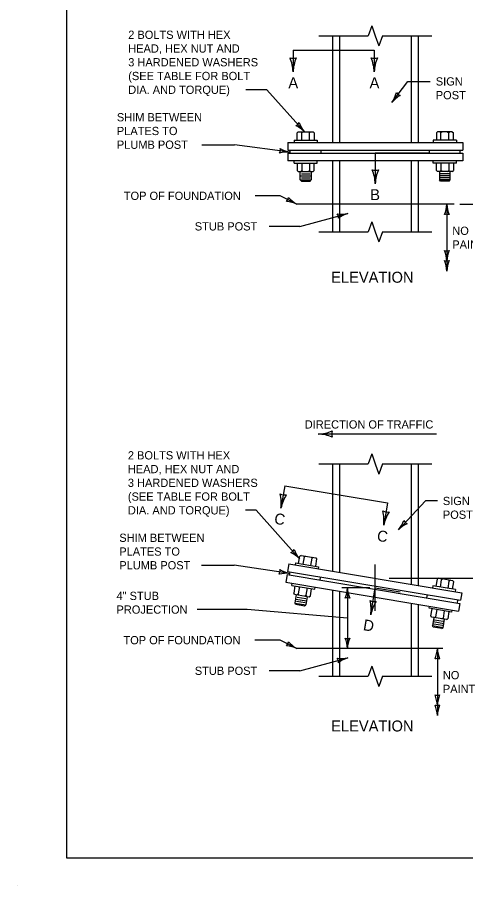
# Model space of a CAD drawing. Extents: x 49991.4 to 50021, y 49987.6 to 50011.4.
# Drawn here: x 49999.02 to 50002.29, y 49987.6 to 49993.92 of the extents above; entities that cross this region are included whole.
import ezdxf

# ---------------------------------------------------------------- set-up
doc = ezdxf.new("R2010")
doc.units = 0
for name, color, linetype in [('Level 1', 7, 'Continuous'), ('Level 2', 7, 'Continuous'), ('Level 3', 7, 'Continuous'), ('Level 5', 7, 'Continuous'), ('Level 6', 7, 'Continuous')]:
    doc.layers.add(name, color=color, linetype=linetype)

msp = doc.modelspace()

# ---------------------------------------------------------------- linework, layer by layer
at = {"layer": 'Level 1'}
for p, q in [((50001.3176, 49993.7824), (50001.3176, 49993.0073)), ((50001.3693, 49993.7824), (50001.3693, 49993.0073)), ((50001.8899, 49993.7824), (50001.8899, 49993.0073)), ((50001.9416, 49993.7824), (50001.9416, 49993.0073)), ((50001.069, 49993.0832), (50001.0615, 49993.0757)), ((50001.0615, 49993.0223), (50001.0615, 49993.0757)), ((50001.069, 49993.0832), (50001.1777, 49993.0832)), ((50001.0877, 49993.0832), (50001.0952, 49993.0757)), ((50001.1028, 49993.0832), (50001.0952, 49993.0757)), ((50001.0952, 49993.0223), (50001.0952, 49993.0757)), ((50001.144, 49993.0832), (50001.1515, 49993.0757)), ((50001.159, 49993.0832), (50001.1515, 49993.0757)), ((50001.1515, 49993.0223), (50001.1515, 49993.0757)), ((50001.1777, 49993.0832), (50001.1852, 49993.0757)), ((50001.1852, 49993.0757), (50001.1852, 49993.0223)), ((50002.0815, 49993.0832), (50002.074, 49993.0757)), ((50002.074, 49993.0757), (50002.074, 49993.0223)), ((50002.1902, 49993.0832), (50002.0815, 49993.0832)), ((50002.1002, 49993.0832), (50002.1077, 49993.0757)), ((50002.1152, 49993.0832), (50002.1077, 49993.0757)), ((50002.1077, 49993.0223), (50002.1077, 49993.0757)), ((50002.1564, 49993.0832), (50002.164, 49993.0757)), ((50002.1715, 49993.0832), (50002.164, 49993.0757)), ((50002.164, 49993.0223), (50002.164, 49993.0757)), ((50002.1902, 49993.0832), (50002.1977, 49993.0757)), ((50002.1977, 49993.0223), (50002.1977, 49993.0757)), ((50000.9922, 49993.0073), (50002.267, 49993.0073)), ((50000.9922, 49993.0073), (50000.9922, 49992.9512)), ((50001.039, 49993.0223), (50001.2077, 49993.0223)), ((50001.039, 49993.0223), (50001.039, 49993.0073)), ((50001.2077, 49993.0223), (50001.2077, 49993.0073)), ((50002.2202, 49993.0223), (50002.0515, 49993.0223)), ((50002.0515, 49993.0223), (50002.0515, 49993.0073)), ((50002.2202, 49993.0223), (50002.2202, 49993.0073)), ((50002.267, 49993.0073), (50002.267, 49992.9512)), ((50000.9922, 49992.9512), (50002.267, 49992.9512)), ((50000.9922, 49992.928), (50002.267, 49992.928)), ((50000.9922, 49992.928), (50000.9922, 49992.8717)), ((50001.0109, 49992.928), (50001.0109, 49992.9512)), ((50001.2359, 49992.928), (50001.2359, 49992.9512)), ((50002.0233, 49992.928), (50002.0233, 49992.9512)), ((50002.2483, 49992.928), (50002.2483, 49992.9512)), ((50002.267, 49992.928), (50002.267, 49992.8717)), ((50002.267, 49992.8717), (50000.9922, 49992.8717)), ((50001.039, 49992.8568), (50001.039, 49992.8717)), ((50001.039, 49992.8568), (50001.2077, 49992.8568)), ((50001.0615, 49992.8568), (50001.0615, 49992.8033)), ((50001.0952, 49992.8568), (50001.0952, 49992.8033)), ((50001.1515, 49992.8568), (50001.1515, 49992.8033)), ((50001.1852, 49992.8033), (50001.1852, 49992.8568)), ((50001.2077, 49992.8568), (50001.2077, 49992.8717)), ((50001.3176, 49992.8717), (50001.3176, 49992.3555)), ((50001.3693, 49992.8717), (50001.3693, 49992.3555)), ((50001.8899, 49992.8717), (50001.8899, 49992.3555)), ((50001.9416, 49992.8717), (50001.9416, 49992.3555)), ((50002.0515, 49992.8568), (50002.0515, 49992.8717)), ((50002.2202, 49992.8568), (50002.0515, 49992.8568)), ((50002.074, 49992.8033), (50002.074, 49992.8568)), ((50002.1077, 49992.8568), (50002.1077, 49992.8033)), ((50002.164, 49992.8568), (50002.164, 49992.8033)), ((50002.1977, 49992.8568), (50002.1977, 49992.8033)), ((50002.2202, 49992.8568), (50002.2202, 49992.8717)), ((50001.069, 49992.7959), (50001.0615, 49992.8033)), ((50001.069, 49992.7959), (50001.1777, 49992.7959)), ((50001.084, 49992.7335), (50001.084, 49992.7959)), ((50001.0877, 49992.7959), (50001.0952, 49992.8033)), ((50001.1028, 49992.7959), (50001.0952, 49992.8033)), ((50001.144, 49992.7959), (50001.1515, 49992.8033)), ((50001.159, 49992.7959), (50001.1515, 49992.8033)), ((50001.1628, 49992.7959), (50001.1628, 49992.7335)), ((50001.1777, 49992.7959), (50001.1852, 49992.8033)), ((50002.0815, 49992.7959), (50002.074, 49992.8033)), ((50002.1902, 49992.7959), (50002.0815, 49992.7959)), ((50002.0964, 49992.7959), (50002.0964, 49992.7335)), ((50002.1002, 49992.7959), (50002.1077, 49992.8033)), ((50002.1152, 49992.7959), (50002.1077, 49992.8033)), ((50002.1564, 49992.7959), (50002.164, 49992.8033)), ((50002.1715, 49992.7959), (50002.164, 49992.8033)), ((50002.1752, 49992.7335), (50002.1752, 49992.7959)), ((50002.1902, 49992.7959), (50002.1977, 49992.8033)), ((50001.084, 49992.7635), (50001.1628, 49992.7635)), ((50001.0915, 49992.7259), (50001.084, 49992.7335)), ((50001.084, 49992.7335), (50001.1628, 49992.7335)), ((50001.0915, 49992.7784), (50001.1552, 49992.7784)), ((50001.0915, 49992.7484), (50001.1552, 49992.7484)), ((50001.0915, 49992.7259), (50001.1552, 49992.7259)), ((50001.1552, 49992.7259), (50001.1628, 49992.7335)), ((50002.1752, 49992.7635), (50002.0964, 49992.7635)), ((50002.104, 49992.7259), (50002.0964, 49992.7335)), ((50002.1752, 49992.7335), (50002.0964, 49992.7335)), ((50002.1677, 49992.7784), (50002.104, 49992.7784)), ((50002.1677, 49992.7484), (50002.104, 49992.7484)), ((50002.1677, 49992.7259), (50002.104, 49992.7259)), ((50002.1677, 49992.7259), (50002.1752, 49992.7335)), ((50002.2046, 49992.5575), (50001.0586, 49992.5575)), ((50001.3176, 49990.6669), (50001.3176, 49989.8871)), ((50001.3693, 49990.6669), (50001.3693, 49989.8784)), ((50001.8899, 49990.6669), (50001.8899, 49989.7918)), ((50001.9416, 49990.6669), (50001.9416, 49989.7832)), ((50001.0494, 49989.9471), (50001.047, 49989.9322)), ((50001.0494, 49989.9471), (50001.216, 49989.9192)), ((50001.0717, 49989.9432), (50001.0804, 49989.996)), ((50001.089, 49990.0022), (50001.0804, 49989.996)), ((50001.089, 49990.0022), (50001.1963, 49989.9843)), ((50001.105, 49989.9377), (50001.1137, 49989.9904)), ((50001.1076, 49989.999), (50001.1137, 49989.9904)), ((50001.1224, 49989.9965), (50001.1137, 49989.9904)), ((50001.1605, 49989.9286), (50001.1692, 49989.9812)), ((50001.163, 49989.9898), (50001.1692, 49989.9812)), ((50001.1778, 49989.9874), (50001.1692, 49989.9812)), ((50001.2025, 49989.9756), (50001.1938, 49989.923)), ((50001.1963, 49989.9843), (50001.2025, 49989.9756)), ((50001.0008, 49989.9399), (50000.9916, 49989.8844)), ((50000.9916, 49989.8844), (50002.2492, 49989.6749)), ((50001.0008, 49989.9399), (50002.2584, 49989.7304)), ((50001.0062, 49989.8585), (50001.01, 49989.8813)), ((50001.216, 49989.9192), (50001.2134, 49989.9045)), ((50000.9877, 49989.8616), (50000.9785, 49989.8062)), ((50000.9877, 49989.8616), (50002.2453, 49989.6521)), ((50001.2282, 49989.8216), (50001.232, 49989.8444)), ((50002.0792, 49989.8296), (50002.0704, 49989.7769)), ((50002.0879, 49989.8357), (50002.0792, 49989.8296)), ((50002.195, 49989.8178), (50002.0879, 49989.8357)), ((50002.1037, 49989.7714), (50002.1125, 49989.824)), ((50002.1064, 49989.8326), (50002.1125, 49989.824)), ((50002.1211, 49989.8302), (50002.1125, 49989.824)), ((50002.1618, 49989.8235), (50002.1679, 49989.8148)), ((50002.1766, 49989.821), (50002.1679, 49989.8148)), ((50002.195, 49989.8178), (50002.2012, 49989.8092)), ((50000.9785, 49989.8062), (50002.2362, 49989.5967)), ((50001.0223, 49989.7836), (50001.0247, 49989.7985)), ((50001.0223, 49989.7836), (50001.1887, 49989.7559)), ((50001.0445, 49989.78), (50001.0357, 49989.7274)), ((50001.0777, 49989.7745), (50001.069, 49989.7217)), ((50001.1332, 49989.7652), (50001.1245, 49989.7126)), ((50001.1578, 49989.707), (50001.1665, 49989.7596)), ((50001.1887, 49989.7559), (50001.1912, 49989.7707)), ((50002.0483, 49989.7806), (50002.0458, 49989.7659)), ((50002.2146, 49989.7529), (50002.0483, 49989.7806)), ((50002.1592, 49989.762), (50002.1679, 49989.8148)), ((50002.1925, 49989.7565), (50002.2012, 49989.8092)), ((50002.2146, 49989.7529), (50002.2122, 49989.738)), ((50001.0418, 49989.7187), (50001.0357, 49989.7274)), ((50001.0418, 49989.7187), (50001.1491, 49989.7008)), ((50001.0464, 49989.6546), (50001.0566, 49989.7162)), ((50001.0603, 49989.7156), (50001.069, 49989.7217)), ((50001.0612, 49989.6977), (50001.124, 49989.6873)), ((50001.0751, 49989.7131), (50001.069, 49989.7217)), ((50001.1159, 49989.7064), (50001.1245, 49989.7126)), ((50001.1344, 49989.7032), (50001.124, 49989.6417)), ((50001.1306, 49989.704), (50001.1245, 49989.7126)), ((50001.1491, 49989.7008), (50001.1578, 49989.707)), ((50001.3176, 49989.7497), (50001.3176, 49989.122)), ((50001.3693, 49989.741), (50001.3693, 49989.122)), ((50002.005, 49989.6922), (50002.0087, 49989.715)), ((50002.2584, 49989.7304), (50002.2492, 49989.6749)), ((50001.0525, 49989.646), (50001.0464, 49989.6546)), ((50001.0464, 49989.6546), (50001.124, 49989.6417)), ((50001.0513, 49989.6843), (50001.129, 49989.6713)), ((50001.0525, 49989.646), (50001.1154, 49989.6356)), ((50001.0562, 49989.6682), (50001.1191, 49989.6578)), ((50001.1154, 49989.6356), (50001.124, 49989.6417)), ((50001.8899, 49989.6543), (50001.8899, 49989.122)), ((50001.9416, 49989.6456), (50001.9416, 49989.122)), ((50002.0209, 49989.6173), (50002.0234, 49989.6321)), ((50002.2268, 49989.6552), (50002.2307, 49989.678)), ((50002.2453, 49989.6521), (50002.2362, 49989.5967)), ((50002.1875, 49989.5895), (50002.0209, 49989.6173)), ((50002.0344, 49989.5609), (50002.0432, 49989.6136)), ((50002.0765, 49989.608), (50002.0677, 49989.5554)), ((50002.132, 49989.5988), (50002.1232, 49989.5462)), ((50002.1653, 49989.5932), (50002.1565, 49989.5405)), ((50002.1875, 49989.5895), (50002.1899, 49989.6044)), ((50002.0406, 49989.5523), (50002.0344, 49989.5609)), ((50002.1479, 49989.5344), (50002.0406, 49989.5523)), ((50002.0554, 49989.5499), (50002.0452, 49989.4882)), ((50002.1277, 49989.5049), (50002.05, 49989.5178)), ((50002.1179, 49989.4913), (50002.055, 49989.5018)), ((50002.0591, 49989.5492), (50002.0677, 49989.5554)), ((50002.1228, 49989.5208), (50002.0599, 49989.5314)), ((50002.0738, 49989.5468), (50002.0677, 49989.5554)), ((50002.1145, 49989.54), (50002.1232, 49989.5462)), ((50002.1228, 49989.4752), (50002.133, 49989.5369)), ((50002.1294, 49989.5375), (50002.1232, 49989.5462)), ((50002.1479, 49989.5344), (50002.1565, 49989.5405)), ((50002.0513, 49989.4796), (50002.0452, 49989.4882)), ((50002.1228, 49989.4752), (50002.0452, 49989.4882)), ((50002.1142, 49989.4691), (50002.0513, 49989.4796)), ((50002.1142, 49989.4691), (50002.1228, 49989.4752)), ((50002.1214, 49989.324), (50001.0586, 49989.324)), ((49999.0245, 49987.5988), (49999.0245, 49987.5988))]:
    msp.add_line(p, q, dxfattribs=at)
msp.add_lwpolyline([(49999.3835, 49998.9992), (50016.7501, 49998.9992), (50016.7501, 49987.7988), (49999.3835, 49987.7988)], close=True, dxfattribs=at)
at = {"layer": 'Level 3'}
for p, q in [((50001.7508, 49993.298), (50001.8658, 49993.4507)), ((50001.8658, 49993.4507), (50002.0299, 49993.4507)), ((50000.8398, 49993.3901), (50000.6876, 49993.3901)), ((50001.1148, 49993.0832), (50000.8398, 49993.3901)), ((50000.3679, 49992.9901), (50000.6057, 49992.9901)), ((50001.0109, 49992.9354), (50000.6057, 49992.9901)), ((50000.9384, 49992.6184), (50000.756, 49992.6184)), ((50001.0586, 49992.5575), (50000.9384, 49992.6184)), ((50002.1501, 49992.5575), (50002.1501, 49992.0704)), ((50002.2446, 49992.5575), (50002.5649, 49992.5575)), ((50001.0796, 49992.3959), (50001.4302, 49992.4906)), ((50001.0796, 49992.3959), (50000.8577, 49992.3959)), ((50002.0762, 49990.8848), (50001.2147, 49990.8848)), ((50001.9939, 49990.3979), (50001.7983, 49990.1885)), ((50002.0814, 49990.3979), (50001.9939, 49990.3979)), ((50000.7619, 49990.3299), (50000.685, 49990.3299)), ((50001.0772, 49989.9768), (50000.7619, 49990.3299)), ((50000.3653, 49989.9299), (50000.6029, 49989.9299)), ((50001.0082, 49989.8704), (50000.6029, 49989.9299)), ((50001.7296, 49989.8352), (50002.4683, 49989.8352)), ((50001.5896, 49989.7664), (50001.3867, 49989.7664)), ((50001.4267, 49989.7664), (50001.4267, 49989.324)), ((50000.6981, 49989.6074), (50000.3334, 49989.6074)), ((50001.4267, 49989.5452), (50000.6981, 49989.6074)), ((50000.9384, 49989.3849), (50000.7534, 49989.3849)), ((50001.0586, 49989.324), (50000.9384, 49989.3849)), ((50002.0814, 49989.324), (50002.0814, 49988.8369)), ((50001.0796, 49989.1624), (50001.4302, 49989.2571)), ((50001.0796, 49989.1624), (50000.8577, 49989.1624))]:
    msp.add_line(p, q, dxfattribs=at)
for centre, radius, start, end in [((50001.558, 49993.4288), 0.233, 325.84352, 345.09337), ((50001.8279, 49993.4004), 0.0548, 215.15503, 250.87739), ((50001.9227, 49993.1571), 0.2223, 120.47222, 140.65572), ((50001.0293, 49993.1787), 0.0548, 294.00341, 329.72577), ((50000.9492, 49992.9193), 0.233, 44.6919, 63.94175), ((50001.2864, 49993.2246), 0.2223, 199.3206, 219.50411), ((50000.8838, 49992.9525), 0.0548, 334.44826, 10.17063), ((50000.9911, 49992.7032), 0.233, 85.13676, 104.38661), ((50001.0497, 49993.1543), 0.2223, 239.76546, 259.94896), ((50000.9442, 49992.6154), 0.0548, 315.26951, 350.99187), ((50001.1672, 49992.7515), 0.2223, 220.5867, 240.77021), ((50000.9637, 49992.3447), 0.233, 65.958, 85.20785), ((50001.928, 49992.5667), 0.2223, 337.45601, 357.63952), ((50002.3828, 49992.569), 0.233, 182.82731, 202.07716), ((50001.3811, 49992.7074), 0.2223, 262.57138, 282.75488), ((50001.3064, 49992.4572), 0.0548, 357.25418, 32.97654), ((50001.502, 49992.2689), 0.233, 107.94268, 127.19253), ((50002.1501, 49992.4293), 0.0548, 72.13882, 107.86118), ((50002.1501, 49992.2721), 0.0548, 252.13882, 287.86118), ((50001.9174, 49992.1323), 0.233, 2.82731, 22.07716), ((50002.3722, 49992.1347), 0.2223, 157.45601, 177.63952), ((50002.1501, 49992.1986), 0.0548, 252.13882, 287.86118), ((50001.9174, 49992.0589), 0.233, 2.82731, 22.07716), ((50002.3722, 49992.0612), 0.2223, 157.45601, 177.63952), ((50001.1994, 49991.1951), 0.3107, 272.82731, 292.07716), ((50001.3857, 49990.8848), 0.073, 162.13882, 197.86118), ((50001.2025, 49990.5886), 0.2964, 67.45601, 87.63952), ((50001.6204, 49990.3389), 0.233, 319.78348, 339.03333), ((50001.9544, 49990.0302), 0.2223, 114.41218, 134.59569), ((50001.8858, 49990.2822), 0.0548, 209.09499, 244.81735), ((50000.9918, 49990.0724), 0.0548, 293.90202, 329.62438), ((50000.9113, 49989.8132), 0.233, 44.59051, 63.84036), ((50001.249, 49990.1179), 0.2223, 199.21921, 219.40272), ((50000.8813, 49989.889), 0.0548, 333.78807, 9.51043), ((50001.0495, 49990.0889), 0.2223, 239.10526, 259.28877), ((50000.9858, 49989.6385), 0.233, 84.47656, 103.72641), ((50001.2046, 49989.7756), 0.2223, 337.45601, 357.63952), ((50001.6594, 49989.7779), 0.233, 182.82731, 202.07716), ((50001.4267, 49989.6382), 0.0548, 72.13882, 107.86118), ((50000.9442, 49989.3819), 0.0548, 315.26951, 350.99187), ((50001.1672, 49989.518), 0.2223, 220.5867, 240.77021), ((50001.4267, 49989.4522), 0.0548, 252.13882, 287.86118), ((50001.194, 49989.3125), 0.233, 2.82731, 22.07716), ((50001.6488, 49989.3148), 0.2223, 157.45601, 177.63952), ((50000.9637, 49989.1112), 0.233, 65.958, 85.20785), ((50001.8592, 49989.3332), 0.2223, 337.45601, 357.63952), ((50002.3141, 49989.3355), 0.233, 182.82731, 202.07716), ((50001.3811, 49989.4739), 0.2223, 262.57138, 282.75488), ((50001.3064, 49989.2237), 0.0548, 357.25418, 32.97654), ((50001.502, 49989.0354), 0.233, 107.94268, 127.19253), ((50002.0814, 49989.1958), 0.0548, 72.13882, 107.86118), ((50002.0814, 49989.0386), 0.0548, 252.13882, 287.86118), ((50001.8487, 49988.8988), 0.233, 2.82731, 22.07716), ((50002.3035, 49988.9012), 0.2223, 157.45601, 177.63952), ((50002.0814, 49988.9651), 0.0548, 252.13882, 287.86118), ((50001.8487, 49988.8254), 0.233, 2.82731, 22.07716), ((50002.3035, 49988.8277), 0.2223, 157.45601, 177.63952)]:
    msp.add_arc(centre, radius, start, end, dxfattribs=at)
at = {"layer": 'Level 5'}
msp.add_line((50001.6296, 49989.5977), (50001.6296, 49989.9352), dxfattribs=at)
at = {"layer": 'Level 6'}
for p, q in [((50001.6037, 49993.8555), (50001.5778, 49993.7824)), ((50001.6037, 49993.8555), (50001.6296, 49993.7824)), ((50001.2176, 49993.7824), (50001.5778, 49993.7824)), ((50001.6296, 49993.7824), (50001.6555, 49993.7093)), ((50001.6814, 49993.7824), (50001.6555, 49993.7093)), ((50001.6814, 49993.7824), (50002.0416, 49993.7824)), ((50001.0313, 49993.6789), (50001.6222, 49993.6789)), ((50001.0313, 49993.6789), (50001.0313, 49993.5207)), ((50001.6222, 49993.6789), (50001.6222, 49993.5207)), ((50001.6037, 49992.4286), (50001.5778, 49992.3555)), ((50001.6037, 49992.4286), (50001.6296, 49992.3555)), ((50001.2176, 49992.3555), (50001.5778, 49992.3555)), ((50001.6296, 49992.3555), (50001.6555, 49992.2824)), ((50001.6814, 49992.3555), (50001.6555, 49992.2824)), ((50001.6814, 49992.3555), (50002.0416, 49992.3555)), ((50001.6037, 49990.74), (50001.5778, 49990.6669)), ((50001.6037, 49990.74), (50001.6296, 49990.6669)), ((50001.2176, 49990.6669), (50001.5778, 49990.6669)), ((50001.6296, 49990.6669), (50001.6555, 49990.5938)), ((50001.6814, 49990.6669), (50001.6555, 49990.5938)), ((50001.6814, 49990.6669), (50002.0416, 49990.6669)), ((50000.9701, 49990.5084), (50000.943, 49990.3458)), ((50000.9701, 49990.5084), (50001.7178, 49990.3839)), ((50001.7178, 49990.3839), (50001.6907, 49990.2214)), ((50001.5969, 49989.5704), (50001.6296, 49989.7664)), ((50001.6296, 49989.7664), (50001.8107, 49989.7363)), ((50001.6037, 49989.1951), (50001.5778, 49989.122)), ((50001.6037, 49989.1951), (50001.6296, 49989.122)), ((50001.2176, 49989.122), (50001.5778, 49989.122)), ((50001.6296, 49989.122), (50001.6555, 49989.0489)), ((50001.6814, 49989.122), (50001.6555, 49989.0489)), ((50001.6814, 49989.122), (50002.0416, 49989.122))]:
    msp.add_line(p, q, dxfattribs=at)
msp.add_lwpolyline([(50002.0233, 49992.928), (50001.6296, 49992.928), (50001.6296, 49992.7066)], dxfattribs=at)
for centre, radius, start, end in [((50001.0313, 49993.6917), 0.073, 252.13882, 287.86118), ((50000.721, 49993.5054), 0.3107, 2.82731, 22.07716), ((50001.3275, 49993.5085), 0.2964, 157.45601, 177.63952), ((50001.6222, 49993.6917), 0.073, 252.13882, 287.86118), ((50001.3119, 49993.5054), 0.3107, 2.82731, 22.07716), ((50001.9184, 49993.5085), 0.2964, 157.45601, 177.63952), ((50001.6296, 49992.8776), 0.073, 252.13882, 287.86118), ((50001.3193, 49992.6913), 0.3107, 2.82731, 22.07716), ((50001.9258, 49992.6944), 0.2964, 157.45601, 177.63952), ((50000.9711, 49990.5144), 0.073, 242.6765, 278.39886), ((50000.6344, 49990.3817), 0.3107, 353.36499, 12.61484), ((50001.2331, 49990.2851), 0.2964, 147.99369, 168.1772), ((50001.7188, 49990.39), 0.073, 242.67078, 278.39314), ((50001.3821, 49990.2573), 0.3107, 353.35927, 12.60912), ((50001.9808, 49990.1606), 0.2964, 147.98797, 168.17148), ((50001.625, 49989.739), 0.073, 242.66702, 278.38938), ((50001.2883, 49989.6063), 0.3107, 353.35551, 12.60536), ((50001.887, 49989.5096), 0.2964, 147.98421, 168.16772)]:
    msp.add_arc(centre, radius, start, end, dxfattribs=at)

# ---------------------------------------------------------------- texts
at = {"layer": 'Level 2'}
for s, height, p in [('2 BOLTS WITH HEX', 0.06, (49999.8314, 49993.7601)), ('HEAD, HEX NUT AND', 0.06, (49999.8314, 49993.6601)), ('3 HARDENED WASHERS', 0.06, (49999.8314, 49993.5601)), ('(SEE TABLE FOR BOLT', 0.06, (49999.8314, 49993.4601)), ('A', 0.08, (50000.997, 49993.4007)), ('A', 0.08, (50001.5879, 49993.4007)), ('SIGN', 0.06, (50002.0699, 49993.4207)), ('DIA. AND TORQUE)', 0.06, (49999.8314, 49993.3601)), ('POST', 0.06, (50002.0699, 49993.3207)), ('SHIM BETWEEN', 0.06, (49999.7487, 49993.1601)), ('PLATES TO', 0.06, (49999.7487, 49993.0601)), ('PLUMB POST', 0.06, (49999.7487, 49992.9601)), ('B', 0.08, (50001.5926, 49992.5866)), ('TOP OF FOUNDATION', 0.06, (49999.7993, 49992.5884)), ('STUB POST', 0.06, (50000.316, 49992.3659)), ('NO', 0.06, (50002.1901, 49992.334)), ('PAINT', 0.06, (50002.1901, 49992.234)), ('ELEVATION', 0.08, (50001.3079, 49991.9858)), ('DIRECTION OF TRAFFIC', 0.06, (50001.1162, 49990.9248)), ('2 BOLTS WITH HEX', 0.06, (49999.8288, 49990.6999)), ('HEAD, HEX NUT AND', 0.06, (49999.8288, 49990.5999)), ('3 HARDENED WASHERS', 0.06, (49999.8288, 49990.4999)), ('(SEE TABLE FOR BOLT', 0.06, (49999.8288, 49990.3999)), ('SIGN', 0.06, (50002.1214, 49990.3679)), ('DIA. AND TORQUE)', 0.06, (49999.8288, 49990.2999)), ('POST', 0.06, (50002.1214, 49990.2679)), ('SHIM BETWEEN', 0.06, (49999.7663, 49990.0999)), ('PLATES TO', 0.06, (49999.7663, 49989.9999)), ('PLUMB POST', 0.06, (49999.7663, 49989.8999)), ('4" STUB', 0.06, (49999.7461, 49989.6774)), ('PROJECTION', 0.06, (49999.7461, 49989.5774)), ('TOP OF FOUNDATION', 0.06, (49999.7967, 49989.3549)), ('STUB POST', 0.06, (50000.316, 49989.1324)), ('NO', 0.06, (50002.1214, 49989.1004)), ('PAINT', 0.06, (50002.1214, 49989.0004)), ('ELEVATION', 0.08, (50001.3079, 49988.7204))]:
    msp.add_text(s, height=height, dxfattribs=at).set_placement(p)
for s, p in [('C', (50000.8897, 49990.233)), ('C', (50001.6374, 49990.1086)), ('D', (50001.5369, 49989.4587))]:
    msp.add_text(s, height=0.08, rotation=350.55, dxfattribs=at).set_placement(p)

doc.saveas('drawing.dxf')
